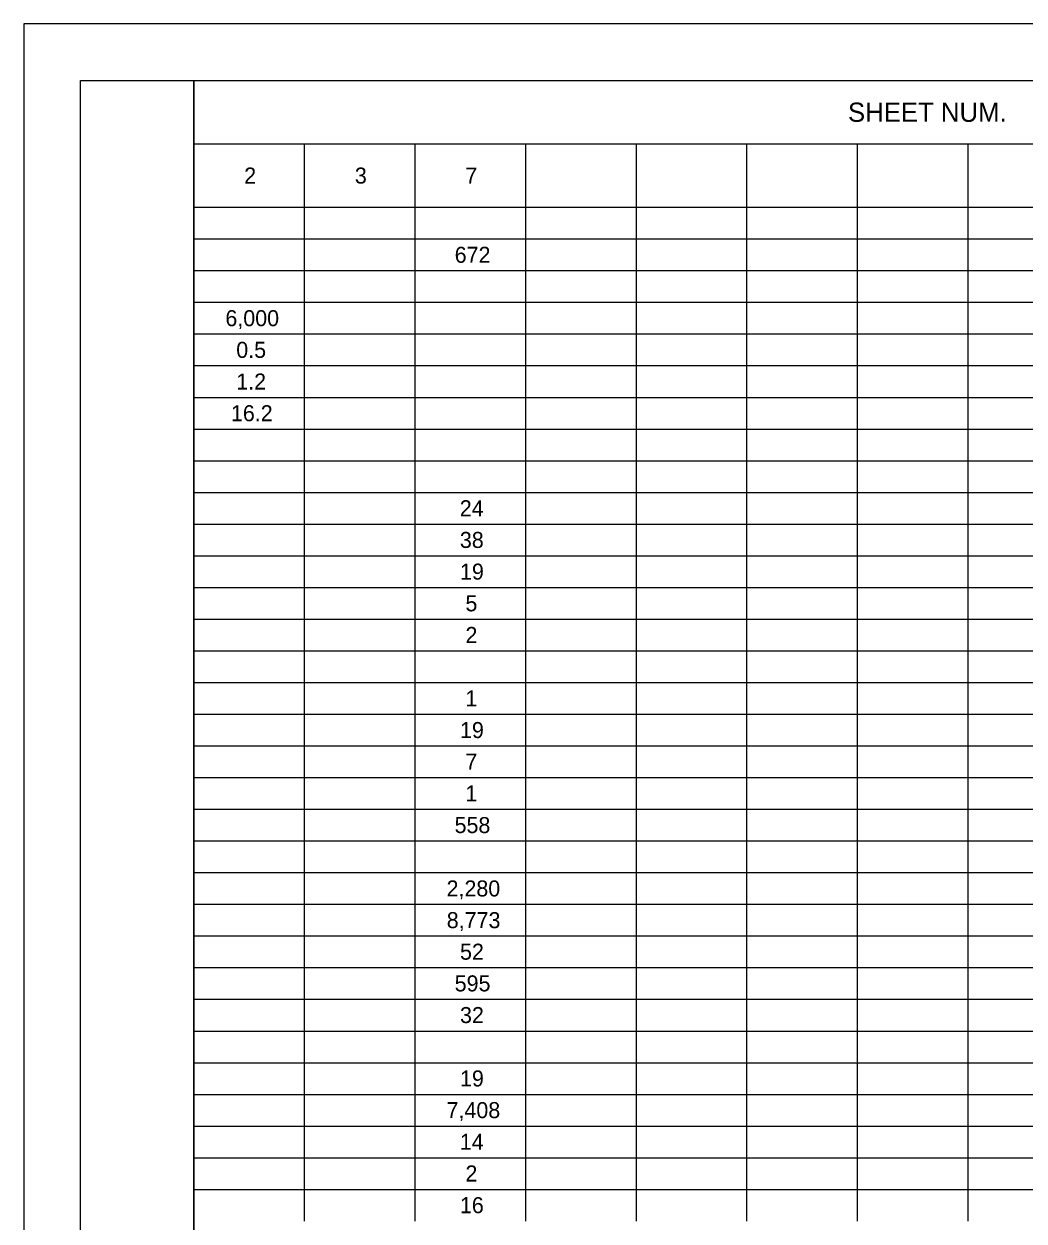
# Model space of a CAD drawing. Extents: x 0 to 34, y 0 to 22.
# Drawn here: x 0 to 8.84, y 11.42 to 22 of the extents above; entities that cross this region are included whole.
import ezdxf

# ---------------------------------------------------------------- set-up
doc = ezdxf.new("R2010")
doc.units = 0
for name, color, linetype in [('Default', 7, 'Continuous'), ('SH_Border', 7, 'Continuous'), ('SH_Cut_Line', 7, 'Continuous')]:
    doc.layers.add(name, color=color, linetype=linetype)

msp = doc.modelspace()

# ---------------------------------------------------------------- linework, layer by layer
at = {"layer": 'Default'}
for p, q in [((1.5, 21.5), (2.477, 21.5)), ((1.5, 21.5), (1.5, 21.22)), ((2.477, 21.5), (4.431, 21.5)), ((4.431, 21.5), (5.408, 21.5)), ((5.408, 21.5), (6.385, 21.5)), ((6.385, 21.5), (7.362, 21.5)), ((7.362, 21.5), (8.339, 21.5)), ((8.339, 21.5), (13.224, 21.5)), ((1.5, 21.22), (1.5, 20.94)), ((1.5, 20.94), (2.477, 20.94)), ((1.5, 20.94), (1.5, 20.66)), ((2.477, 20.94), (4.431, 20.94)), ((2.477, 20.94), (2.477, 20.66)), ((3.454, 20.94), (3.454, 20.66)), ((4.431, 20.94), (5.408, 20.94)), ((4.431, 20.94), (4.431, 20.66)), ((5.408, 20.94), (6.385, 20.94)), ((5.408, 20.94), (5.408, 20.66)), ((6.385, 20.94), (7.362, 20.94)), ((6.385, 20.94), (6.385, 20.66)), ((7.362, 20.94), (8.339, 20.94)), ((7.362, 20.94), (7.362, 20.66)), ((8.339, 20.94), (13.224, 20.94)), ((8.339, 20.94), (8.339, 20.66)), ((1.5, 20.66), (1.5, 20.38)), ((2.477, 20.66), (2.477, 20.38)), ((3.454, 20.66), (3.454, 20.38)), ((4.431, 20.66), (4.431, 20.38)), ((5.408, 20.66), (5.408, 20.38)), ((6.385, 20.66), (6.385, 20.38)), ((7.362, 20.66), (7.362, 20.38)), ((8.339, 20.66), (8.339, 20.38)), ((1.5, 20.38), (2.477, 20.38)), ((1.5, 20.38), (1.5, 20.1)), ((2.477, 20.38), (4.431, 20.38)), ((2.477, 20.38), (2.477, 20.1)), ((3.454, 20.38), (3.454, 20.1)), ((4.431, 20.38), (5.408, 20.38)), ((4.431, 20.38), (4.431, 20.1)), ((5.408, 20.38), (6.385, 20.38)), ((5.408, 20.38), (5.408, 20.1)), ((6.385, 20.38), (7.362, 20.38)), ((6.385, 20.38), (6.385, 20.1)), ((7.362, 20.38), (8.339, 20.38)), ((7.362, 20.38), (7.362, 20.1)), ((8.339, 20.38), (13.224, 20.38)), ((8.339, 20.38), (8.339, 20.1)), ((1.5, 20.1), (2.477, 20.1)), ((1.5, 20.1), (1.5, 18.7)), ((2.477, 20.1), (4.431, 20.1)), ((2.477, 20.1), (2.477, 18.7)), ((3.454, 20.1), (3.454, 18.7)), ((4.431, 20.1), (5.408, 20.1)), ((4.431, 20.1), (4.431, 18.7)), ((5.408, 20.1), (6.385, 20.1)), ((5.408, 20.1), (5.408, 18.7)), ((6.385, 20.1), (7.362, 20.1)), ((6.385, 20.1), (6.385, 18.7)), ((7.362, 20.1), (8.339, 20.1)), ((7.362, 20.1), (7.362, 18.7)), ((8.339, 20.1), (13.224, 20.1)), ((8.339, 20.1), (8.339, 18.7)), ((1.5, 19.82), (2.477, 19.82)), ((2.477, 19.82), (4.431, 19.82)), ((4.431, 19.82), (5.408, 19.82)), ((5.408, 19.82), (6.385, 19.82)), ((6.385, 19.82), (7.362, 19.82)), ((7.362, 19.82), (8.339, 19.82)), ((8.339, 19.82), (13.224, 19.82)), ((1.5, 19.54), (2.477, 19.54)), ((2.477, 19.54), (4.431, 19.54)), ((4.431, 19.54), (5.408, 19.54)), ((5.408, 19.54), (6.385, 19.54)), ((6.385, 19.54), (7.362, 19.54)), ((7.362, 19.54), (8.339, 19.54)), ((8.339, 19.54), (13.224, 19.54)), ((1.5, 19.26), (2.477, 19.26)), ((2.477, 19.26), (4.431, 19.26)), ((4.431, 19.26), (5.408, 19.26)), ((5.408, 19.26), (6.385, 19.26)), ((6.385, 19.26), (7.362, 19.26)), ((7.362, 19.26), (8.339, 19.26)), ((8.339, 19.26), (13.224, 19.26)), ((1.5, 18.98), (2.477, 18.98)), ((2.477, 18.98), (4.431, 18.98)), ((4.431, 18.98), (5.408, 18.98)), ((5.408, 18.98), (6.385, 18.98)), ((6.385, 18.98), (7.362, 18.98)), ((7.362, 18.98), (8.339, 18.98)), ((8.339, 18.98), (13.224, 18.98)), ((1.5, 18.7), (2.477, 18.7)), ((1.5, 18.7), (1.5, 18.14)), ((2.477, 18.7), (4.431, 18.7)), ((2.477, 18.7), (2.477, 18.14)), ((3.454, 18.7), (3.454, 18.14)), ((4.431, 18.7), (5.408, 18.7)), ((4.431, 18.7), (4.431, 18.14)), ((5.408, 18.7), (6.385, 18.7)), ((5.408, 18.7), (5.408, 18.14)), ((6.385, 18.7), (7.362, 18.7)), ((6.385, 18.7), (6.385, 18.14)), ((7.362, 18.7), (8.339, 18.7)), ((7.362, 18.7), (7.362, 18.14)), ((8.339, 18.7), (13.224, 18.7)), ((8.339, 18.7), (8.339, 18.14)), ((1.5, 18.42), (2.477, 18.42)), ((2.477, 18.42), (4.431, 18.42)), ((4.431, 18.42), (5.408, 18.42)), ((5.408, 18.42), (6.385, 18.42)), ((6.385, 18.42), (7.362, 18.42)), ((7.362, 18.42), (8.339, 18.42)), ((8.339, 18.42), (13.224, 18.42)), ((1.5, 18.14), (2.477, 18.14)), ((1.5, 18.14), (1.5, 17.86)), ((2.477, 18.14), (4.431, 18.14)), ((2.477, 18.14), (2.477, 17.86)), ((3.454, 18.14), (3.454, 17.86)), ((4.431, 18.14), (5.408, 18.14)), ((4.431, 18.14), (4.431, 17.86)), ((5.408, 18.14), (6.385, 18.14)), ((5.408, 18.14), (5.408, 17.86)), ((6.385, 18.14), (7.362, 18.14)), ((6.385, 18.14), (6.385, 17.86)), ((7.362, 18.14), (8.339, 18.14)), ((7.362, 18.14), (7.362, 17.86)), ((8.339, 18.14), (13.224, 18.14)), ((8.339, 18.14), (8.339, 17.86)), ((1.5, 17.86), (2.477, 17.86)), ((1.5, 17.86), (1.5, 17.58)), ((2.477, 17.86), (4.431, 17.86)), ((2.477, 17.86), (2.477, 17.58)), ((3.454, 17.86), (3.454, 17.58)), ((4.431, 17.86), (5.408, 17.86)), ((4.431, 17.86), (4.431, 17.58)), ((5.408, 17.86), (6.385, 17.86)), ((5.408, 17.86), (5.408, 17.58)), ((6.385, 17.86), (7.362, 17.86)), ((6.385, 17.86), (6.385, 17.58)), ((7.362, 17.86), (8.339, 17.86)), ((7.362, 17.86), (7.362, 17.58)), ((8.339, 17.86), (13.224, 17.86)), ((8.339, 17.86), (8.339, 17.58)), ((1.5, 17.58), (2.477, 17.58)), ((1.5, 17.58), (1.5, 17.3)), ((2.477, 17.58), (4.431, 17.58)), ((2.477, 17.58), (2.477, 17.3)), ((3.454, 17.58), (3.454, 17.3)), ((4.431, 17.58), (5.408, 17.58)), ((4.431, 17.58), (4.431, 17.3)), ((5.408, 17.58), (6.385, 17.58)), ((5.408, 17.58), (5.408, 17.3)), ((6.385, 17.58), (7.362, 17.58)), ((6.385, 17.58), (6.385, 17.3)), ((7.362, 17.58), (8.339, 17.58)), ((7.362, 17.58), (7.362, 17.3)), ((8.339, 17.58), (13.224, 17.58)), ((8.339, 17.58), (8.339, 17.3)), ((1.5, 17.3), (2.477, 17.3)), ((1.5, 17.3), (1.5, 17.02)), ((2.477, 17.3), (4.431, 17.3)), ((2.477, 17.3), (2.477, 17.02)), ((3.454, 17.3), (3.454, 17.02)), ((4.431, 17.3), (5.408, 17.3)), ((4.431, 17.3), (4.431, 17.02)), ((5.408, 17.3), (6.385, 17.3)), ((5.408, 17.3), (5.408, 17.02)), ((6.385, 17.3), (7.362, 17.3)), ((6.385, 17.3), (6.385, 17.02)), ((7.362, 17.3), (8.339, 17.3)), ((7.362, 17.3), (7.362, 17.02)), ((8.339, 17.3), (13.224, 17.3)), ((8.339, 17.3), (8.339, 17.02)), ((1.5, 17.02), (2.477, 17.02)), ((1.5, 17.02), (1.5, 16.74)), ((2.477, 17.02), (4.431, 17.02)), ((2.477, 17.02), (2.477, 16.74)), ((3.454, 17.02), (3.454, 16.74)), ((4.431, 17.02), (5.408, 17.02)), ((4.431, 17.02), (4.431, 16.74)), ((5.408, 17.02), (6.385, 17.02)), ((5.408, 17.02), (5.408, 16.74)), ((6.385, 17.02), (7.362, 17.02)), ((6.385, 17.02), (6.385, 16.74)), ((7.362, 17.02), (8.339, 17.02)), ((7.362, 17.02), (7.362, 16.74)), ((8.339, 17.02), (13.224, 17.02)), ((8.339, 17.02), (8.339, 16.74)), ((1.5, 16.74), (2.477, 16.74)), ((1.5, 16.74), (1.5, 16.18)), ((2.477, 16.74), (4.431, 16.74)), ((2.477, 16.74), (2.477, 16.18)), ((3.454, 16.74), (3.454, 16.18)), ((4.431, 16.74), (5.408, 16.74)), ((4.431, 16.74), (4.431, 16.18)), ((5.408, 16.74), (6.385, 16.74)), ((5.408, 16.74), (5.408, 16.18)), ((6.385, 16.74), (7.362, 16.74)), ((6.385, 16.74), (6.385, 16.18)), ((7.362, 16.74), (8.339, 16.74)), ((7.362, 16.74), (7.362, 16.18)), ((8.339, 16.74), (13.224, 16.74)), ((8.339, 16.74), (8.339, 16.18)), ((1.5, 16.46), (2.477, 16.46)), ((2.477, 16.46), (4.431, 16.46)), ((4.431, 16.46), (5.408, 16.46)), ((5.408, 16.46), (6.385, 16.46)), ((6.385, 16.46), (7.362, 16.46)), ((7.362, 16.46), (8.339, 16.46)), ((8.339, 16.46), (13.224, 16.46)), ((1.5, 16.18), (2.477, 16.18)), ((1.5, 16.18), (1.5, 15.9)), ((2.477, 16.18), (4.431, 16.18)), ((2.477, 16.18), (2.477, 15.9)), ((3.454, 16.18), (3.454, 15.9)), ((4.431, 16.18), (5.408, 16.18)), ((4.431, 16.18), (4.431, 15.9)), ((5.408, 16.18), (6.385, 16.18)), ((5.408, 16.18), (5.408, 15.9)), ((6.385, 16.18), (7.362, 16.18)), ((6.385, 16.18), (6.385, 15.9)), ((7.362, 16.18), (8.339, 16.18)), ((7.362, 16.18), (7.362, 15.9)), ((8.339, 16.18), (13.224, 16.18)), ((8.339, 16.18), (8.339, 15.9)), ((1.5, 15.9), (2.477, 15.9)), ((1.5, 15.9), (1.5, 15.62)), ((2.477, 15.9), (4.431, 15.9)), ((2.477, 15.9), (2.477, 15.62)), ((3.454, 15.9), (3.454, 15.62)), ((4.431, 15.9), (5.408, 15.9)), ((4.431, 15.9), (4.431, 15.62)), ((5.408, 15.9), (6.385, 15.9)), ((5.408, 15.9), (5.408, 15.62)), ((6.385, 15.9), (7.362, 15.9)), ((6.385, 15.9), (6.385, 15.62)), ((7.362, 15.9), (8.339, 15.9)), ((7.362, 15.9), (7.362, 15.62)), ((8.339, 15.9), (13.224, 15.9)), ((8.339, 15.9), (8.339, 15.62)), ((1.5, 15.62), (2.477, 15.62)), ((1.5, 15.62), (1.5, 15.34)), ((2.477, 15.62), (4.431, 15.62)), ((2.477, 15.62), (2.477, 15.34)), ((3.454, 15.62), (3.454, 15.34)), ((4.431, 15.62), (5.408, 15.62)), ((4.431, 15.62), (4.431, 15.34)), ((5.408, 15.62), (6.385, 15.62)), ((5.408, 15.62), (5.408, 15.34)), ((6.385, 15.62), (7.362, 15.62)), ((6.385, 15.62), (6.385, 15.34)), ((7.362, 15.62), (8.339, 15.62)), ((7.362, 15.62), (7.362, 15.34)), ((8.339, 15.62), (13.224, 15.62)), ((8.339, 15.62), (8.339, 15.34)), ((1.5, 15.34), (2.477, 15.34)), ((1.5, 15.34), (1.5, 14.78)), ((2.477, 15.34), (4.431, 15.34)), ((2.477, 15.34), (2.477, 14.78)), ((3.454, 15.34), (3.454, 14.78)), ((4.431, 15.34), (5.408, 15.34)), ((4.431, 15.34), (4.431, 14.78)), ((5.408, 15.34), (6.385, 15.34)), ((5.408, 15.34), (5.408, 14.78)), ((6.385, 15.34), (7.362, 15.34)), ((6.385, 15.34), (6.385, 14.78)), ((7.362, 15.34), (8.339, 15.34)), ((7.362, 15.34), (7.362, 14.78)), ((8.339, 15.34), (13.224, 15.34)), ((8.339, 15.34), (8.339, 14.78)), ((1.5, 15.06), (2.477, 15.06)), ((2.477, 15.06), (4.431, 15.06)), ((4.431, 15.06), (5.408, 15.06)), ((5.408, 15.06), (6.385, 15.06)), ((6.385, 15.06), (7.362, 15.06)), ((7.362, 15.06), (8.339, 15.06)), ((8.339, 15.06), (13.224, 15.06)), ((1.5, 14.78), (2.477, 14.78)), ((1.5, 14.78), (1.5, 14.5)), ((2.477, 14.78), (4.431, 14.78)), ((2.477, 14.78), (2.477, 14.5)), ((3.454, 14.78), (3.454, 14.5)), ((4.431, 14.78), (5.408, 14.78)), ((4.431, 14.78), (4.431, 14.5)), ((5.408, 14.78), (6.385, 14.78)), ((5.408, 14.78), (5.408, 14.5)), ((6.385, 14.78), (7.362, 14.78)), ((6.385, 14.78), (6.385, 14.5)), ((7.362, 14.78), (8.339, 14.78)), ((7.362, 14.78), (7.362, 14.5)), ((8.339, 14.78), (13.224, 14.78)), ((8.339, 14.78), (8.339, 14.5)), ((1.5, 14.5), (2.477, 14.5)), ((1.5, 14.5), (1.5, 14.22)), ((2.477, 14.5), (4.431, 14.5)), ((2.477, 14.5), (2.477, 14.22)), ((3.454, 14.5), (3.454, 14.22)), ((4.431, 14.5), (5.408, 14.5)), ((4.431, 14.5), (4.431, 14.22)), ((5.408, 14.5), (6.385, 14.5)), ((5.408, 14.5), (5.408, 14.22)), ((6.385, 14.5), (7.362, 14.5)), ((6.385, 14.5), (6.385, 14.22)), ((7.362, 14.5), (8.339, 14.5)), ((7.362, 14.5), (7.362, 14.22)), ((8.339, 14.5), (13.224, 14.5)), ((8.339, 14.5), (8.339, 14.22)), ((1.5, 14.22), (2.477, 14.22)), ((1.5, 14.22), (1.5, 13.94)), ((2.477, 14.22), (4.431, 14.22)), ((2.477, 14.22), (2.477, 13.94)), ((3.454, 14.22), (3.454, 13.94)), ((4.431, 14.22), (5.408, 14.22)), ((4.431, 14.22), (4.431, 13.94)), ((5.408, 14.22), (6.385, 14.22)), ((5.408, 14.22), (5.408, 13.94)), ((6.385, 14.22), (7.362, 14.22)), ((6.385, 14.22), (6.385, 13.94)), ((7.362, 14.22), (8.339, 14.22)), ((7.362, 14.22), (7.362, 13.94)), ((8.339, 14.22), (13.224, 14.22)), ((8.339, 14.22), (8.339, 13.94)), ((1.5, 13.94), (2.477, 13.94)), ((1.5, 13.94), (1.5, 11.7)), ((2.477, 13.94), (4.431, 13.94)), ((2.477, 13.94), (2.477, 11.7)), ((3.454, 13.94), (3.454, 11.7)), ((4.431, 13.94), (5.408, 13.94)), ((4.431, 13.94), (4.431, 11.7)), ((5.408, 13.94), (6.385, 13.94)), ((5.408, 13.94), (5.408, 11.7)), ((6.385, 13.94), (7.362, 13.94)), ((6.385, 13.94), (6.385, 11.7)), ((7.362, 13.94), (8.339, 13.94)), ((7.362, 13.94), (7.362, 11.7)), ((8.339, 13.94), (13.224, 13.94)), ((8.339, 13.94), (8.339, 11.7)), ((1.5, 13.66), (2.477, 13.66)), ((2.477, 13.66), (4.431, 13.66)), ((4.431, 13.66), (5.408, 13.66)), ((5.408, 13.66), (6.385, 13.66)), ((6.385, 13.66), (7.362, 13.66)), ((7.362, 13.66), (8.339, 13.66)), ((8.339, 13.66), (13.224, 13.66)), ((1.5, 13.38), (2.477, 13.38)), ((2.477, 13.38), (4.431, 13.38)), ((4.431, 13.38), (5.408, 13.38)), ((5.408, 13.38), (6.385, 13.38)), ((6.385, 13.38), (7.362, 13.38)), ((7.362, 13.38), (8.339, 13.38)), ((8.339, 13.38), (13.224, 13.38)), ((1.5, 13.1), (2.477, 13.1)), ((2.477, 13.1), (4.431, 13.1)), ((4.431, 13.1), (5.408, 13.1)), ((5.408, 13.1), (6.385, 13.1)), ((6.385, 13.1), (7.362, 13.1)), ((7.362, 13.1), (8.339, 13.1)), ((8.339, 13.1), (13.224, 13.1)), ((1.5, 12.82), (2.477, 12.82)), ((2.477, 12.82), (4.431, 12.82)), ((4.431, 12.82), (5.408, 12.82)), ((5.408, 12.82), (6.385, 12.82)), ((6.385, 12.82), (7.362, 12.82)), ((7.362, 12.82), (8.339, 12.82)), ((8.339, 12.82), (13.224, 12.82)), ((1.5, 12.54), (2.477, 12.54)), ((2.477, 12.54), (4.431, 12.54)), ((4.431, 12.54), (5.408, 12.54)), ((5.408, 12.54), (6.385, 12.54)), ((6.385, 12.54), (7.362, 12.54)), ((7.362, 12.54), (8.339, 12.54)), ((8.339, 12.54), (13.224, 12.54)), ((1.5, 12.26), (2.477, 12.26)), ((2.477, 12.26), (4.431, 12.26)), ((4.431, 12.26), (5.408, 12.26)), ((5.408, 12.26), (6.385, 12.26)), ((6.385, 12.26), (7.362, 12.26)), ((7.362, 12.26), (8.339, 12.26)), ((8.339, 12.26), (13.224, 12.26)), ((1.5, 11.98), (2.477, 11.98)), ((2.477, 11.98), (4.431, 11.98)), ((4.431, 11.98), (5.408, 11.98)), ((5.408, 11.98), (6.385, 11.98)), ((6.385, 11.98), (7.362, 11.98)), ((7.362, 11.98), (8.339, 11.98)), ((8.339, 11.98), (13.224, 11.98)), ((1.5, 11.7), (2.477, 11.7)), ((1.5, 11.7), (1.5, 11.42)), ((2.477, 11.7), (4.431, 11.7)), ((2.477, 11.7), (2.477, 11.42)), ((3.454, 11.7), (3.454, 11.42)), ((4.431, 11.7), (5.408, 11.7)), ((4.431, 11.7), (4.431, 11.42)), ((5.408, 11.7), (6.385, 11.7)), ((5.408, 11.7), (5.408, 11.42)), ((6.385, 11.7), (7.362, 11.7)), ((6.385, 11.7), (6.385, 11.42)), ((7.362, 11.7), (8.339, 11.7)), ((7.362, 11.7), (7.362, 11.42)), ((8.339, 11.7), (13.224, 11.7)), ((8.339, 11.7), (8.339, 11.42))]:
    msp.add_line(p, q, dxfattribs=at)
at = {"layer": 'SH_Border'}
for points in [[(0.5, 21.5), (1.5, 21.5), (1.5, 0.5), (0.5, 0.5)], [(1.5, 21.5), (33.5, 21.5), (33.5, 0.5), (1.5, 0.5)]]:
    msp.add_lwpolyline(points, close=True, dxfattribs=at)
at = {"layer": 'SH_Cut_Line'}
msp.add_lwpolyline([(0, 0), (34, 0), (34, 22), (0, 22)], close=True, dxfattribs=at)

# ---------------------------------------------------------------- texts
at = {"layer": 'Default'}
for s, height, p in [('SHEET NUM.', 0.17, (7.281, 21.135)), ('2', 0.142, (1.946, 20.589)), ('3', 0.142, (2.924, 20.589)), ('7', 0.142, (3.9, 20.589)), ('672', 0.1417, (3.806, 19.889)), ('6,000', 0.1417, (1.78, 19.329)), ('0.5', 0.1417, (1.876, 19.049)), ('1.2', 0.1417, (1.876, 18.769)), ('16.2', 0.1417, (1.829, 18.489)), ('24', 0.1417, (3.851, 17.649)), ('38', 0.1417, (3.852, 17.369)), ('19', 0.1417, (3.853, 17.089)), ('5', 0.142, (3.901, 16.809)), ('2', 0.142, (3.901, 16.529)), ('1', 0.142, (3.9, 15.969)), ('19', 0.1417, (3.853, 15.689)), ('7', 0.142, (3.9, 15.409)), ('1', 0.142, (3.9, 15.129)), ('558', 0.1417, (3.805, 14.849)), ('2,280', 0.1417, (3.734, 14.289)), ('8,773', 0.1417, (3.736, 14.009)), ('52', 0.1417, (3.853, 13.73)), ('595', 0.1417, (3.806, 13.45)), ('32', 0.1417, (3.853, 13.17)), ('19', 0.1417, (3.853, 12.61)), ('7,408', 0.1417, (3.734, 12.33)), ('14', 0.1417, (3.851, 12.05)), ('2', 0.142, (3.901, 11.77)), ('16', 0.1417, (3.852, 11.49))]:
    msp.add_text(s, height=height, dxfattribs=at).set_placement(p)

doc.saveas('drawing.dxf')
